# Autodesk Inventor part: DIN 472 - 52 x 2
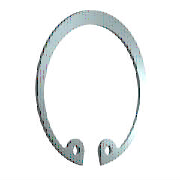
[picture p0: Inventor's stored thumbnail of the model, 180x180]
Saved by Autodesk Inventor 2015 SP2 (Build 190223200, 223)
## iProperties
IsCustomPart: 0
Created: 2012-02
Part Number: DIN 472 - 52 x 2
Material: Stahl, weich
Description: Sicherungsring
Document SubType Name: Modeling
Standard: DIN 472
Designer: Dan
Standards Organization: DIN
Language: de-DE
Size Designation: 52 x 2
Categories: <MemberInstance><Categories><Category DisplayName="Wellenteile" InternalName="7f7aeb1f-a693-4053-b835-cee3144e0d98" Mnemonic="SHFT"><Category DisplayName="Siche
Density: 7.85 g/cm^3
Appearance: Halbpoliert
Author: Dan
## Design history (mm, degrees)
sketch "Skizze1"
  geometry: L1 (0, 13.172)-(0, -61.534) reference; L2 (-38.5, 0)-(38.5, 0) reference; L3 (-4.964, 2.5)-(1.502, 2.5); L4 (0, -2.2)-(-5.307, -2.2); L5 (0, -25)-(-11.662, -49.905); L6 (-11.662, -49.905)-(-25.145, -43.591); L7 (-10.242, -46.871)-(-20.725, -41.962); L8 (-7.978, -47.931)-(-9.35, -50.862); L9 (7.978, -47.931)-(9.35, -50.862); C1 r 1.25 at (-10.242, -46.871); C2 r 1.25 at (10.242, -46.871); A1 r 23.975 centre (0, -26.175) between (14.933, -44.931) and (-14.933, -44.931); A2 r 27.5 centre (0, -25) between (9.35, -50.862) and (-9.35, -50.862); A3 r 2.5 centre (-10.242, -46.871) between (-7.978, -47.931) and (-11.809, -44.923); A4 r 2.5 centre (-13.376, -42.975) between (-14.933, -44.931) and (-11.809, -44.923); A5 r 2.5 centre (13.376, -42.975) between (11.809, -44.923) and (14.933, -44.931); A6 r 2.5 centre (10.242, -46.871) between (11.809, -44.923) and (7.978, -47.931); 3 further points
  constraints: 15 point on circle, 14 end point, 9 symmetric about line, 8 centre point, 6 tangent, 4 coincident, 4 point on line, 3 perpendicular, 1 parallel, 4 other
  dimensions: "d8" = 1.175 distance of A1.centre L5.start (= 0.25 x SRB1); "d38" = 4.7 distance between parallel lines of L4 L3 (= SRB1); "d39" = 25 distance from line of L5.start L2 (= 0.5 x WD); "d43" = 27.5 radius of A2 (= 0.5 x ND); "d45" = 3.35 distance between parallel lines of L7 L6 (= 0.5 x SRB2); "d46" = 2.5 radius of A4 (= SD5); "d47" = 9.35 distance from line of L1 L8.end (= 0.17 x ND); "d48" = 2.5 diameter of C1 (= SD5); "d49" = 2.5 radius of A3 (= SD5)
extrude "Körper" new body sketch "Skizze1" distance "d2" = 2 (= SD); taper "d3" = 0 deg
workaxis "Work Axis1"
workaxis "Work Axis2"
workplane "Work Plane1"
body "Solid1"
other parameters: "SD" = 2 [user parameter; used in 1 equation term], "SRB1" = 4.7 [user parameter; used in 2 equation terms], "ND" = 55 [user parameter; used in 2 equation terms], "SRB2" = 6.7 [user parameter; used in 1 equation term], "SD5" = 2.5 [user parameter; used in 3 equation terms], "d50" = 0, "d51" = 0, "d52" = 0, "d53" = 0, "SD6" = 56.2 [user parameter], "NND" = 52 [user parameter; used in 1 equation term], "WDMAX" = 52 (= NND) [user parameter]
